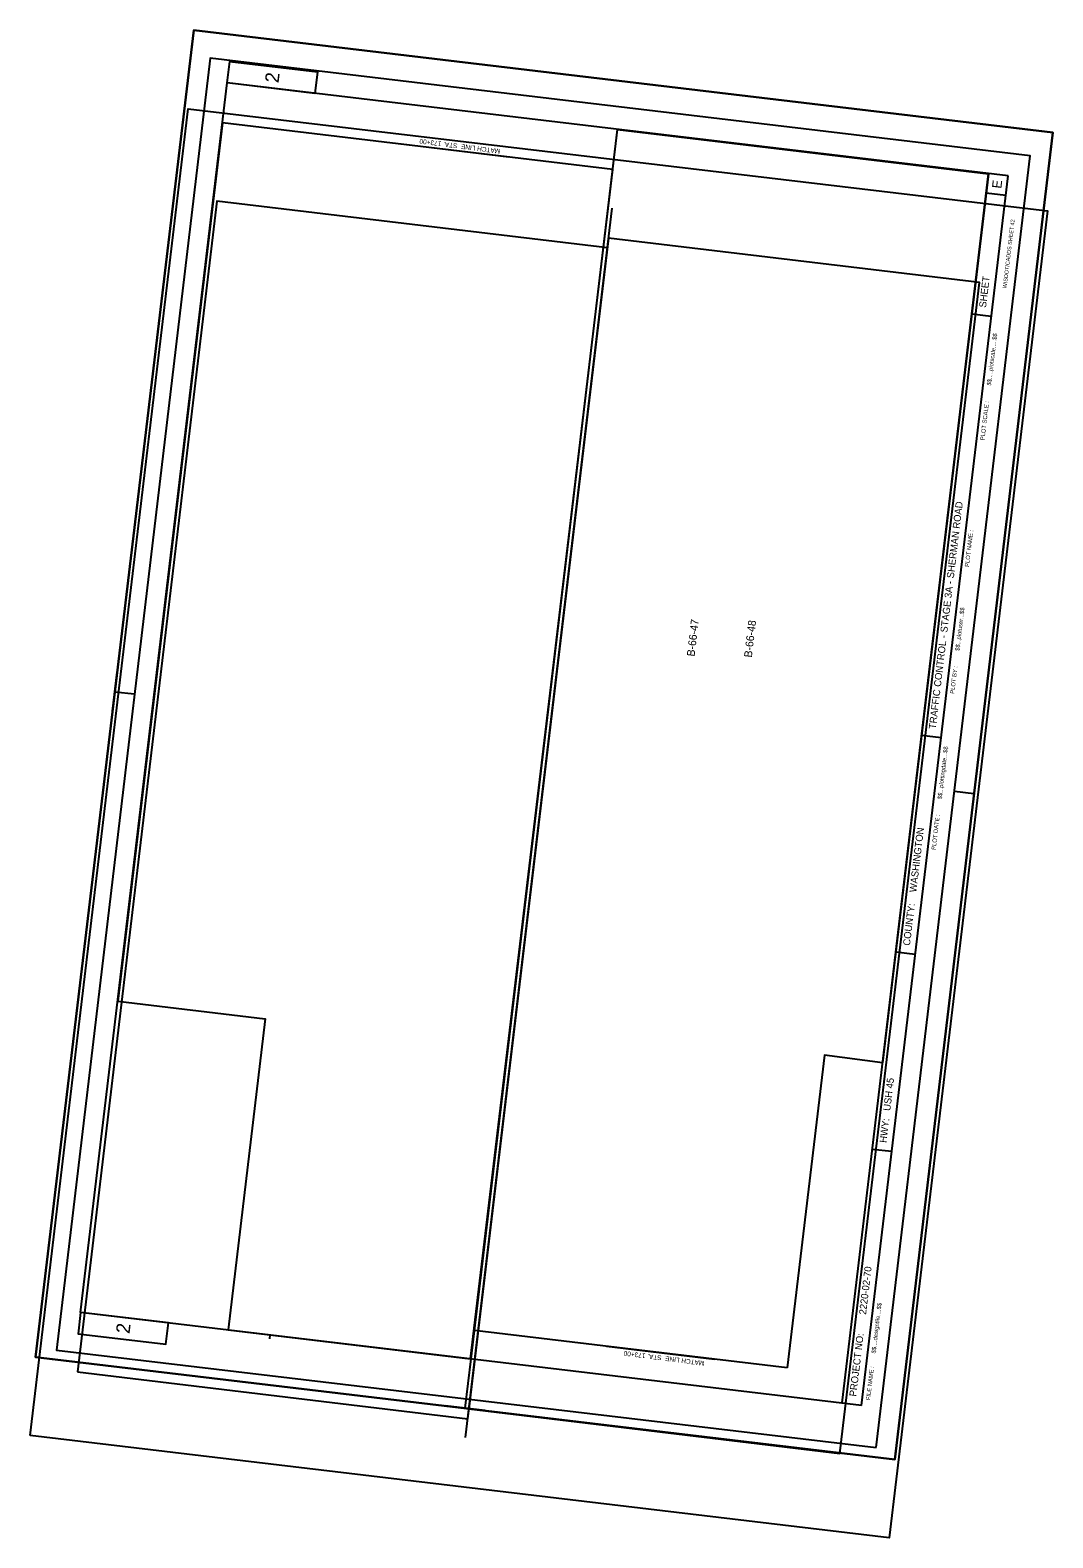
# Model space of a CAD drawing. Extents: x 361130 to 362431, y 140169 to 142087.
import ezdxf

# ---------------------------------------------------------------- set-up
doc = ezdxf.new("R2010")
doc.units = 0
for name, color, linetype in [('Default', 7, 'Continuous'), ('P_ALI_20', 7, 'Continuous'), ('P_ALI_200_Sta', 7, 'Continuous'), ('P_ALI_20_PIData', 7, 'Continuous'), ('P_ALI_20_Sta', 7, 'Continuous'), ('P_ALI_20_Tic', 7, 'Continuous'), ('P_ALI_50_Equation', 7, 'Continuous'), ('P_ALI_50_PIData', 7, 'Continuous'), ('P_ALI_50_Tic', 7, 'Continuous')]:
    doc.layers.add(name, color=color, linetype=linetype)

msp = doc.modelspace()

# ---------------------------------------------------------------- linework, layer by layer
msp.add_lwpolyline([(361130.4, 140299.5), (361331.5, 141987.6), (362423.8, 141857.5), (362222.7, 140169.4), (361130.4, 140299.5)])
at = {"layer": 'Default'}
for points in [[(361190.4, 140380.5), (361686.9, 140321), (361864.3, 141810.6), (361367.8, 141870.1)], [(361190.4, 140380.5), (361686.9, 140321), (361864.3, 141810.6), (361367.8, 141870.1)], [(361190.4, 140380.5), (361686.9, 140321), (361864.3, 141810.6), (361367.8, 141870.1)], [(361688.3, 140333.4), (362160, 140276.9), (362337.4, 141766.3), (361865.7, 141822.8)], [(361688.3, 140333.4), (362160, 140276.9), (362337.4, 141766.3), (361865.7, 141822.8)], [(361688.3, 140333.4), (362160, 140276.9), (362337.4, 141766.3), (361865.7, 141822.8)]]:
    msp.add_lwpolyline(points, close=True, dxfattribs=at)
at = {"layer": 'P_ALI_20'}
for p, q in [((361332.6, 142037.8), (361338.5, 142087.5)), ((361388.1, 142081.6), (361338.5, 142087.5)), ((361194.5, 140456.3), (361380.8, 142020.3)), ((362373.8, 141902), (361380.8, 142020.3)), ((361691, 140397.2), (361877.3, 141961.1)), ((362430.8, 141957.4), (362381.1, 141963.3)), ((362424.8, 141907.7), (362430.8, 141957.4)), ((362162.7, 140341), (362349, 141904.9)), ((362187.5, 140338), (362373.8, 141902)), ((362370.8, 141877.2), (362346, 141880.1)), ((362352.5, 141723.3), (362327.7, 141726.2)), ((361235.3, 141221.1), (361241.2, 141270.8)), ((361238.2, 141245.9), (361263.1, 141243)), ((362288.6, 141187), (362263.8, 141190)), ((362327.6, 141091), (362333.5, 141140.7)), ((362330.5, 141115.8), (362305.7, 141118.8)), ((362255.8, 140911.5), (362231, 140914.4)), ((362226, 140660.8), (362201.1, 140663.7)), ((361137.4, 140399.4), (361143.3, 140449.1)), ((362187.5, 140338), (361194.5, 140456.3)), ((361435.3, 140427.6), (361434.7, 140422.7)), ((361695.5, 140434.4), (361695.5, 140434.4)), ((361187.1, 140393.5), (361137.4, 140399.4)), ((361683.6, 140334.4), (361691, 140397.2)), ((361708.4, 140331.4), (361658.7, 140337.3)), ((362229.7, 140269.3), (362235.6, 140319)), ((362229.7, 140269.3), (362180, 140275.2))]:
    msp.add_line(p, q, dxfattribs=at)
for points in [[(361380.8, 142020.3), (361384.1, 142047.6), (361495.8, 142034.3), (361492.5, 142007)], [(361194.5, 140456.3), (361191.3, 140429), (361303, 140415.7), (361306.3, 140443)]]:
    msp.add_lwpolyline(points, close=True, dxfattribs=at)
at = {"layer": 'P_ALI_200_Sta'}
msp.add_line((361684, 140297.3), (361870.3, 141861.2), dxfattribs=at)
at = {"layer": 'P_ALI_20_PIData'}
for points in [[(361690.2, 140397.1), (361871.3, 141910.4), (361374.8, 141969.6), (361241.7, 140852.3), (361429.4, 140829.9), (361382.3, 140434)], [(362092.9, 140385.7), (362000.5, 140396.7), (361695.3, 140433.1), (361877.3, 141961.1), (362349, 141904.9), (362214.3, 140773.9), (362140.3, 140783.3)]]:
    msp.add_lwpolyline(points, close=True, dxfattribs=at)
at = {"layer": 'P_ALI_20_Tic'}
msp.add_lwpolyline([(361137.4, 140399.4), (361338.5, 142087.5), (362430.8, 141957.4), (362229.7, 140269.3)], close=True, dxfattribs=at)
at = {"layer": 'P_ALI_50_Equation'}
for p, q in [((361602, 141942.7), (361739.2, 141926.2)), ((361863.3, 140413.1), (362000.5, 140396.7))]:
    msp.add_line(p, q, dxfattribs=at)
at = {"layer": 'P_ALI_50_Tic'}
for points in [[(362229.7, 140269.3), (362430.8, 141957.4), (361338.5, 142087.5), (361137.4, 140399.4)], [(362206.3, 140284.2), (362402, 141927.6), (361359.4, 142051.8), (361163.7, 140408.4)]]:
    msp.add_lwpolyline(points, close=True, dxfattribs=at)

# ---------------------------------------------------------------- texts
at = {"layer": 'P_ALI_20'}
for s, height, rotation, p in [('2', 17.5, 83.2076, (361446.2, 142019.7)), ('E', 12, 83.2076, (362365.2, 141885.5)), ('WISDOT/CADDS SHEET 42', 5, 83.2076, (362371.9, 141758.9)), ('SHEET ', 9, 83.2076, (362345.8, 141734.1)), ('$$.....plotscale.....$$', 5.4, 83.2076, (362352.1, 141635.2)), ('PLOT SCALE : ', 5.4, 83.2076, (362343.8, 141565.5)), ('TRAFFIC CONTROL - STAGE 3A - SHERMAN ROAD', 9, 83.2076, (362281.9, 141197.9)), ('PLOT NAME :                      ', 5.4, 83.2076, (362324.1, 141404.4)), ('$$...plotuser...$$', 5.4, 83.2075, (362311.9, 141297.6)), ('PLOT BY :', 5.4, 83.2075, (362305.4, 141243)), ('$$...plottingdate...$$', 5.4, 83.2075, (362289.4, 141108.9)), (' WASHINGTON', 9, 83.2076, (362256.8, 140986.9)), ('PLOT DATE :', 5.4, 83.2075, (362281.7, 141044.4)), ('COUNTY:', 9, 83.2076, (362249.1, 140922.4)), (' USH 45', 9, 83.2076, (362223.6, 140708.9)), ('HWY:', 9, 83.2076, (362219.2, 140671.6)), (' 2220-02-70', 9, 83.2076, (362192.8, 140449.7)), ('$$....designfile....$$', 5.4, 83.2075, (362205.4, 140403.9)), ('2', 17.5, 83.2076, (361256.7, 140428.5)), ('PROJECT NO:', 9, 83.2076, (362180.8, 140348.9)), ('FILE NAME :', 5.4, 83.2076, (362198.3, 140344.3))]:
    msp.add_text(s, height=height, rotation=rotation, dxfattribs=at).set_placement(p)
at = {"layer": 'P_ALI_20_Sta'}
for s, p in [('B-66-47', (361975.2, 141290.3)), ('B-66-48', (362048, 141289))]:
    msp.add_text(s, height=10, rotation=83.3336, dxfattribs=at).set_placement(p)
at = {"layer": 'P_ALI_50_PIData'}
for p in [(361728.4, 141936.2), (361988, 140394.3)]:
    msp.add_text('MATCH LINE  STA. 173+00', height=6, rotation=172.7522, dxfattribs=at).set_placement(p)

doc.saveas('drawing.dxf')
